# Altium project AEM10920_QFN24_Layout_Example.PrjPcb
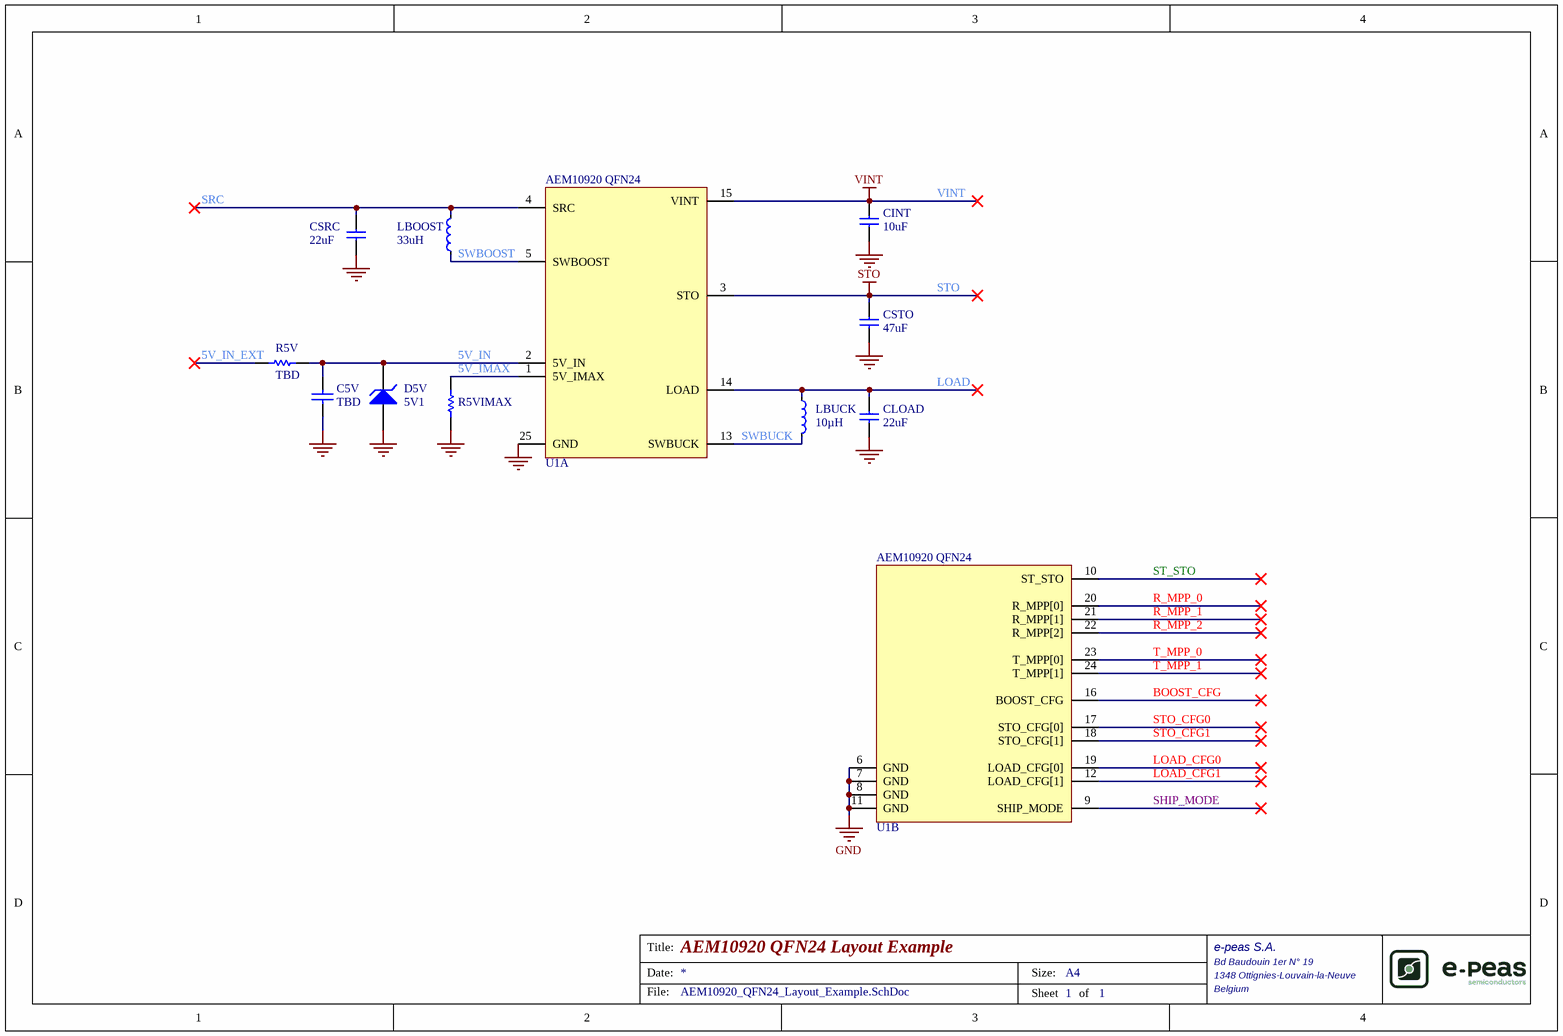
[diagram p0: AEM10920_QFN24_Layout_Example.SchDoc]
Website_Global: https://e-peas.com; Organization_Global: e-peas S.A.; Name: AEM10920 QFN24 Layout Example; Address3_Global: Belgium; Address2_Global: 1348 Ottignies-Louvain-la-Neuve; Address1_Global: Bd Baudouin 1er N° 19
1 sheet, 11 parts. Net scope: global (net labels, ports and power ports of the same name join across sheets).
Board file: AEM10920_QFN24_Layout_Example.PcbDoc

## Sheet AEM10920_QFN24_Layout_Example.SchDoc
size A4; DocumentNumber: 1; SheetNumber: 1; SheetTotal: 1; Organization: e-peas S.A.; Address1: The Gate Business Center; Address2: rue Cattelain 1 b4,; Address3: 1435 Mont-St-Guibert; Address4: Belgium

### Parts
C5V  value TBD  [0603_[1608]]  (hidden comment: Cap Ceramic 0603 TBD)
CINT  10uF  [0402_[1005]]
CLOAD  22uF  [0603_[1608]]
CSRC  22uF  [0603_[1608]]
CSTO  47uF  [0603_[1608]]
D5V  5V1  [SOT23-3P  3x1.40mm Pitch=0.915mm diode AK]
LBOOST  33uH  [Coilcraft-LPS4018]
LBUCK  10µH  [inductor_2520]
R5V  TBD  [Resistor_0603_[1608]]
R5VIMAX  TBD  [Resistor_0603_[1608]]  (value not drawn)
U1  Part Number: AEM10920 QFN24  [QFN24_4x4mm_PITCH_0.5mm_PAD_2.7mm_QP235-00052]  (hidden comment: AEM10920_QFN24)  (parts A,B of 2)

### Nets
GND: C5V.1 CINT.1 CLOAD.1 CSRC.1 CSTO.1 D5V.A R5VIMAX.1 U1.6(GND) U1.7(GND) U1.8(GND) U1.11(GND) U1.25(GND)
STO: CSTO.2 U1.3(STO)
VINT: CINT.2 U1.15(VINT)
5V_IMAX: R5VIMAX.2 U1.1(5V_IMAX)
5V_IN: C5V.2 D5V.K R5V.2 U1.2(5V_IN)
5V_IN_EXT: R5V.1
BOOST_CFG: U1.16(BOOST_CFG)
LOAD: CLOAD.2 LBUCK.1 U1.14(LOAD)
LOAD_CFG0: U1.19(LOAD_CFG[0])
LOAD_CFG1: U1.12(LOAD_CFG[1])
R_MPP_0: U1.20(R_MPP[0])
R_MPP_1: U1.21(R_MPP[1])
R_MPP_2: U1.22(R_MPP[2])
SHIP_MODE: U1.9(SHIP_MODE)
SRC: CSRC.2 LBOOST.2 U1.4(SRC)
ST_STO: U1.10(ST_STO)
STO_CFG0: U1.17(STO_CFG[0])
STO_CFG1: U1.18(STO_CFG[1])
SWBOOST: LBOOST.1 U1.5(SWBOOST)
SWBUCK: LBUCK.2 U1.13(SWBUCK)
T_MPP_0: U1.23(T_MPP[0])
T_MPP_1: U1.24(T_MPP[1])

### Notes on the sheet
- Title:
- Date:
- Size:
- A4
- File:
- Sheet
- of

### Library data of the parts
C5V = Cap Ceramic 0603 TBD: Package Metric: 1608
CINT = Cap Ceramic 10uF, 6.3V, 20%, X5R, 0402: Manuf: MURATA; Manuf PN: GRM155R60J106ME44D; Package Metric: 1005
CLOAD CSRC = Cap Ceramic 22uF, 10V, 20%, X5R 0603: Manuf: MuRata; Manuf PN: GRM188R61A226ME15D; Package Metric: 1608
CSTO = Cap Ceramic 47uF 6.3V +/-20% X5R 0603: Manuf: Murata; Manuf PN: GRM188R60J476ME15D; Package Metric: 1608
D5V = Zener 5.1V 350mW BZX84C5V1-TP: Zener Diode 5.1 V 350 mW ±5% Surface Mount SOT-23; Manuf: Micro Commercial Co; Vbr: 5.1V; I continous: 68mA
LBOOST = Power Inductor 33uH - 0,68A - LPS4018 - Small Symbol: Power Inductor 33uH - 0,68A - LPS4018; Manuf: Coilcraft; Manuf PN: LPS4018-333MRB; Tol: 20%; Rdc: 420mOhms; Self Resonant Frequency: 20MHz; Max DC Current: 800mA
LBUCK = Power Inductor 10µF TDK VLS-CX-1: Manuf PN: VLS252012CX-100M-1; Tol: ±20%; Rdc: 0.482 ohm; Max DC Current: 970 mA
R5V R5VIMAX = Resistor TBD - 0603: Mnt: SMD
U1 = AEM10920 QFN24: Manuf: e-peas; Manuf PN: 10AEM10920A0000; Mnt: SMD; Pitch: 0.5

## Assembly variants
Mounting: not fitted CLOAD2 CSTO2 R1 R2 R3 R4 R5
